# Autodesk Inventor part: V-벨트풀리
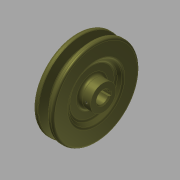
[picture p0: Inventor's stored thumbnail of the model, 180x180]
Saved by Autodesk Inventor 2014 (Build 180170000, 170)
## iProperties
Company: 한국ATC센터
Created: 2015-12
Part Number: V-벨트풀리
Document SubType Name: Modeling
Designer: mdu
Density: 7.25 g/cm^3
Mass: 594.592 g
Surface Area: 210.471 cm^2
Volume: 82.0126 cm^3
Material: 주철
Appearance: 티타늄
Author: mdu
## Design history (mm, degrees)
sketch "스케치1"
  geometry: L1 (-13, 0)-(13, 0); L2 (-13, 0)-(-13, 12.5); L3 (-13, 12.5)-(-9, 12.5); L4 (-9, 12.5)-(-9, 23); L5 (-9, 23)-(-13, 27); L6 (-13, 27)-(-13, 42.7); L7 (-13, 42.7)-(-8.325, 42.7); L8 (-8.325, 42.7)-(-5.574, 33.7); L9 (-5.574, 33.7)-(-1.426, 33.7); L10 (-1.426, 33.7)-(1.325, 42.7); L11 (1.325, 42.7)-(6, 42.7); L12 (6, 42.7)-(6, 27); L13 (6, 27)-(2, 23); L14 (2, 23)-(2, 12.5); L15 (2, 12.5)-(13, 12.5); L16 (13, 12.5)-(13, 0); L17 (-7.5, 40)-(0.5, 40); 2 further points
  constraints: 34 end point, 6 parallel, 5 collinear, 5 equal length, 4 perpendicular, 2 point on line, 1 coincident, 1 horizontal, 1 midpoint
  dimensions: "d0" = 26 distance of L1.start L1.end; "d1" = 2.7 distance between parallel lines of L7 L17; "d2" = 6.3 distance between parallel lines of L9 L17; "d3" = 8 distance of L17.start L17.end; "d4" = 34 deg angle of L10 L8; "d5" = 19 distance between parallel lines of L12 L6; "d7" = 25 diameter of L15 L1; "d8" = 46 diameter of L13.end L1; "d9" = 54 diameter of L12.end L1; "d10" = 4 distance between parallel lines of L2 L4; "d11" = 80 diameter of L17 L1
revolve "회전1" sketch "스케치1" stored, may be unused: angle "d12" = 90 deg
sketch "스케치2"
  geometry: L1 (-2, 5.657)-(-2, 7.8); L2 (-2, 7.8)-(2, 7.8); L3 (2, 7.8)-(2, 5.657); A1 r 6 centre (0, 0) between (-2, 5.657) and (2, 5.657); 1 further point
  constraints: 6 end point, 2 parallel, 2 point on circle, 1 centre point, 1 coincident, 1 perpendicular, 1 vertical
  dimensions: "d13" = 12 diameter of A1; "d14" = 13.8 dimension on A1 L2; "d15" = 4 distance of L1.end L2.end
extrude "돌출1" cut sketch "스케치2" stored distance "d16" = 10; taper "d17" = 0 deg
node "작업 평면1"
sketch "스케치3"
  geometry: L1 (-5.5, 12.5)-(-5.5, -12.5) reference; L2 (20.5, 27)-(20.5, -27) reference; 3 further points
  constraints: 1 horizontal alignment, 1 midpoint
  dimensions: "d18" = 4 distance from line of point (-1.5, 0) L1; "d33" = 22 distance from line of point (-1.5, 0) L2 (derived)
hole "구멍1" sketch "스케치3" at (-1.5, 0) diameter "d19" = 2.459; stored, may be unused: countersink angle "d23" = 90 deg, drill point angle "d25" = 118 deg; dims "d20" = 6, "d21" = 4, "d22" = 2, "d24" = 8
fillet "모깎기1" dims "d26" = 2, "d27" = 0.5, "d28" = 1, "d29" = 3
chamfer "모따기1" distance "d30" = 1; stored, may be unused: second distance "d31" = 2, angle "d32" = 45 deg
node "솔리드1"
